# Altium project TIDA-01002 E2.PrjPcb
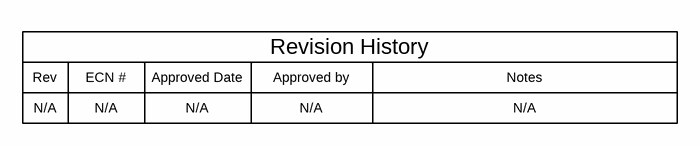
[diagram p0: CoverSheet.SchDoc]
CopyrightYear: 2016; EVM_Orderable: N/A; PCB_Layout: Krypton Solutions; PCB_Rev: E3; PRJ_Customer: Public Release; PRJ_Engineer: Luis Cordova; PRJ_Number: TIDA-01002; PRJ_Title: Automotive 1MP Camera Module with Image Correction; SCH_Rev: E3; TechSupport: http://www.ti.com/support; TID: TIDA-01002
5 sheets, 84 parts. Net scope: flat (ports and power ports of the same name join across sheets).
Board file: TIDA-01002 E2 Layout.PcbDoc
Sheets:
  CoverSheet.SchDoc
  Power over Coax Filter & Power Supply.SchDoc
  ON Semiconductor AS0140AT Imager + ISP.SchDoc
  Serializer.SchDoc
  TID_Hardware.SchDoc

## Sheet CoverSheet.SchDoc
size 431 x 279 mm; Date: Not shown in title block; ApprovedBy: Not shown in title block; CheckedBy: Not shown in title block; Author: Not shown in title block; CompanyName: Not shown in title block; Engineer: Not shown in title block; Organization: Not shown in title block; Address1: Not shown in title block; Address2: Not shown in title block; Address3: Not shown in title block; Address4: Not shown in title block; DocumentNumber: 1; Revision: Use project parameter SCH_Rev; SheetNumber: 1; SheetTotal: 5; PageSetup: Record=PageOptions¦CenterHorizontal=True¦CenterVertical=True¦PrintScale=1.00¦XCorrection=1.00¦YCorrection=1.00¦PrintKind=0¦BorderSize=5000000¦LeftOffset=0¦BottomOffset=0¦Orientation=2¦PaperLength=1000¦PaperWidth=1000¦Scale=100¦PaperSource=15¦PrintQuality=600¦MediaType=1¦DitherType=10¦PaperKind=Letter¦PrintScaleMode=1

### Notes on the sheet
- Rev
- N/A
- ECN #
- Approved Date
- Approved by
- Revision History
- Notes

## Sheet Power over Coax Filter & Power Supply.SchDoc
size 431 x 279 mm; Date: Not shown in title block; ApprovedBy: Not shown in title block; CheckedBy: Not shown in title block; Author: Not shown in title block; CompanyName: Not shown in title block; Engineer: Not shown in title block; Organization: Not shown in title block; Address1: Not shown in title block; Address2: Not shown in title block; Address3: Not shown in title block; Address4: Not shown in title block; DocumentNumber: 1; Revision: Use project parameter SCH_Rev; SheetNumber: 2; SheetTotal: 5; PageSetup: Record=PageOptions¦CenterHorizontal=True¦CenterVertical=True¦PrintScale=1.00¦XCorrection=1.00¦YCorrection=1.00¦PrintKind=0¦BorderSize=5000000¦LeftOffset=0¦BottomOffset=0¦Orientation=2¦PaperLength=1000¦PaperWidth=1000¦Scale=100¦PaperSource=15¦PrintQuality=600¦MediaType=1¦DitherType=10¦PaperKind=Letter¦PrintScaleMode=1
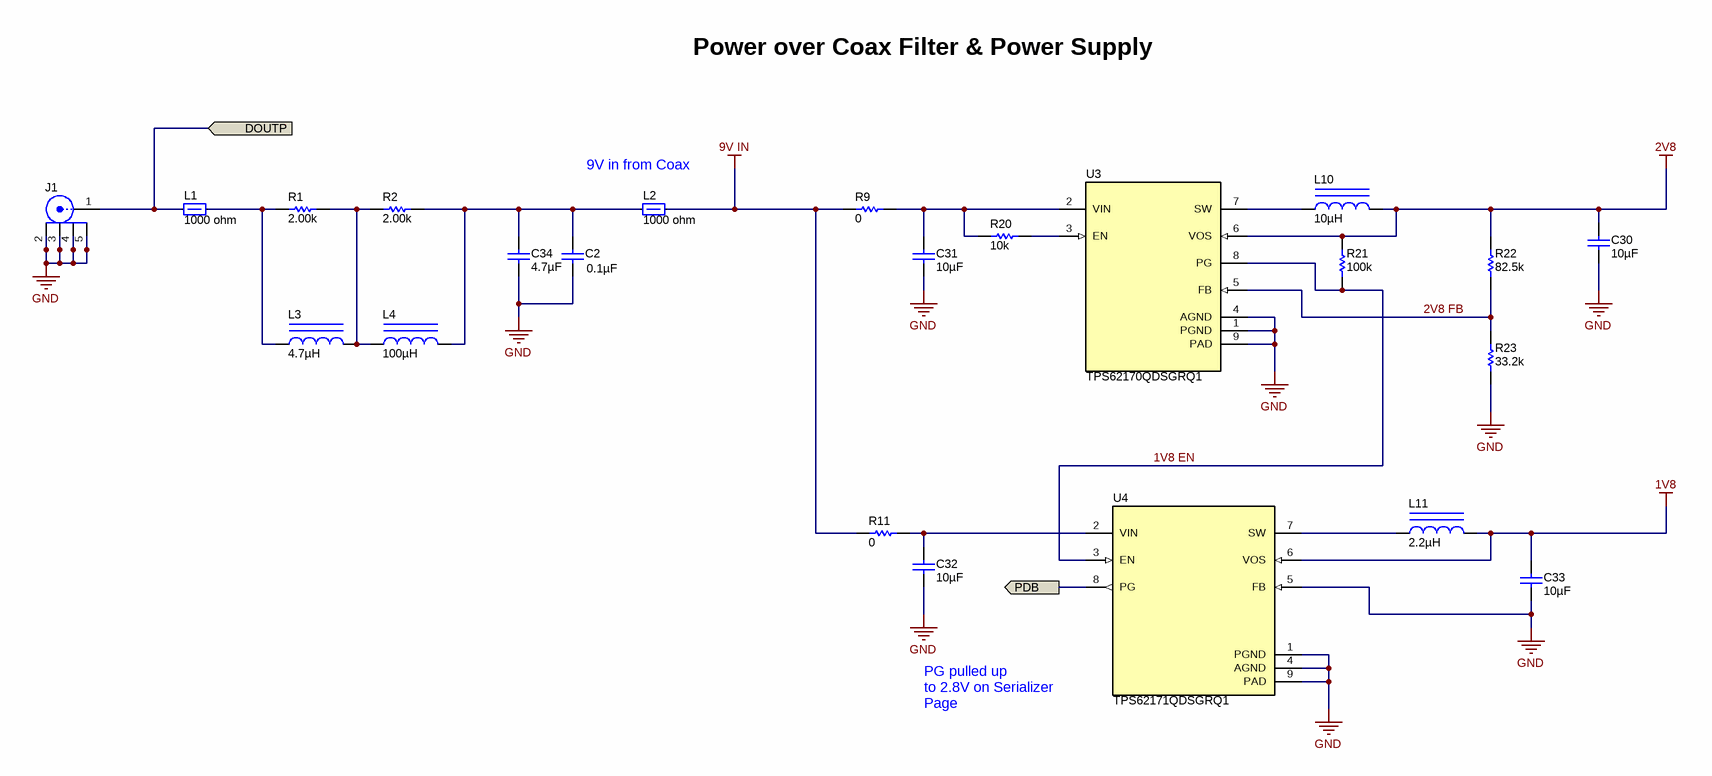
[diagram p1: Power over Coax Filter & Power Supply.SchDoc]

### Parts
C2  value 0.1µF  [0402L]  (hidden comment: C1005X7R1E104K050BB)
C30  ValueDisplayed: 10µF  [0805L]  (hidden comment: GRM21BR71A106KE51L)
C31  ValueDisplayed: 10µF  [0805L]  (hidden comment: CL21B106KOQNNNE)
C32  ValueDisplayed: 10µF  [0805L]  (hidden comment: CL21B106KOQNNNE)
C33  ValueDisplayed: 10µF  [0805L]  (hidden comment: GRM21BR71A106KE51L)
C34  ValueDisplayed: 4.7µF  [0603L]  (hidden comment: GRM188Z71C475KE21D)
J1  59S10H-40ML5-Z  [Rosenberger_59S10H-40ML5-Z]  (value not drawn)
L1  value 1000 ohm  [0402L]  (hidden comment: BLM15AX102SN1D)
L2  value 1000 ohm  [0402L]  (hidden comment: BLM15AX102SN1D)
L3  ValueDisplayed: 4.7µH  [CBC3225]  (hidden comment: CBC3225T4R7MR)
L4  ValueDisplayed: 100µH  [CBC3225]  (hidden comment: CBC3225T101MR)
L10  ValueDisplayed: 10µH  [WE-PMI_1008]  (hidden comment: 74479887310A)
L11  ValueDisplayed: 2.2µH  [WE-PMI-0805_1]  (hidden comment: 74479775222)
R1  ValueDisplayed: 2.00k  [0402L]  (hidden comment: CRCW04022K00FKED)
R2  ValueDisplayed: 2.00k  [0402L]  (hidden comment: CRCW04022K00FKED)
R9  value 0  [0402L]  (hidden comment: CRCW04020000Z0ED)
R11  value 0  [0402L]  (hidden comment: CRCW04020000Z0ED)
R20  ValueDisplayed: 10k  [0402L]  (hidden comment: CRCW040210K0JNED)
R21  ValueDisplayed: 100k  [0402L]  (hidden comment: CRCW0402100KFKED)
R22  ValueDisplayed: 82.5k  [0402L]  (hidden comment: CRCW040282K5FKED)
R23  ValueDisplayed: 33.2k  [0402L]  (hidden comment: CRCW040233K2FKED)
U3  TPS62170QDSGRQ1  [DSG0008A]
U4  TPS62171QDSGRQ1  [DSG0008A]

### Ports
DOUTP, PDB (out)

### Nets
1V8: C33.1 L11.2 U4.6(VOS)
2V8: C30.1 L10.2 R21.2 R22.2 U3.6(VOS)
9V IN: L2.2 R9.2 R11.2
GND: C2.2 C30.2 C31.2 C32.2 C33.2 C34.2 J1.2 J1.3 J1.4 J1.5 R23.1 U3.1(PGND) U3.4(AGND) U3.9(PAD) U4.1(PGND) U4.4(AGND) U4.5(FB) U4.9(PAD)
1V8 EN: R21.1 U3.8(PG) U4.3(EN)
2V8 FB: R22.1 R23.2 U3.5(FB)
DOUTP: J1.1 L1.1 ; port DOUTP
PDB: U4.8(PG) ; port PDB
NetC2_1: C2.1 C34.1 L2.1 L4.2 R2.1
NetC31_1: C31.1 R9.1 R20.1 U3.2(VIN)
NetC32_1: C32.1 R11.1 U4.2(VIN)
NetL1_2: L1.2 L3.1 R1.2
NetL3_2: L3.2 L4.1 R1.1 R2.2
NetL10_1: L10.1 U3.7(SW)
NetL11_1: L11.1 U4.7(SW)
NetR20_2: R20.2 U3.3(EN)

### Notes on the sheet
- Power over Coax Filter & Power Supply
- (near L2) 9V in from Coax
- (near U4) PG pulled up
  to 2.8V on Serializer
  Page

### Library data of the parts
C2 = C1005X7R1E103K: CAP, CERM, 0.1uF, 25V, +/-10%, X7R, 0402; Manufacturer: TDK Corporation; Tolerance_%: ±10%
C30 = GRM21BR71A106KE51L: CAP, CERM, 10uF, 10V, +/-10%, X7R, 0805; Manufacturer: MuRata; Polarized: N; CompType: Capacitor; U/M: EA; Cap_F: 0.00001; Tolerance_%: 10; ESR_Ohm: 0.003; Value1: 0.003 ohm; TaMin_C: -55; TaMax_C: 125; Cap_Case: 0805
C31 C32 = CL21B106KOQNNNE: CAP, CERM, 10 µF, 16 V, +/- 10%, X7R, 0805; Manufacturer: Samsung Electro-Mechanics; Polarized: N; CompType: Capacitor; Value: 10uF; U/M: EA; Cap_F: 0.00001; Tolerance_%: 10; Value1: Unknown; VDC_V: 16; Value2: 16V; TaMin_C: -55; TaMax_C: 125; Cap_Case: 0805; AEC Category: Q200; SizeArea_mm2: 2.5; SizeAreaWB_mm2: 6.75; SizeX_mm: 2; SizeY_mm: 1.25; SizeZ_mm: 1.45
C33 = GRM21BR71A106KE51L: CAP, CERM, 10 µF, 10 V, +/- 10%, X7R, 0805; Manufacturer: MuRata; Polarized: N; CompType: Capacitor; Value: 10uF; U/M: EA; Cap_F: 0.00001; Tolerance_%: 10; ESR_ohm: 0.003; Value1: 0.003 ohm; Value2: 10V; TaMin_C: -55; TaMax_C: 125; Cap_Case: 0805; AEC Category: Q200
C34 = GRM188Z71C475KE21D: CAP, CERM, 4.7 µF, 16 V,+/- 10%, X7R, 0603; Manufacturer: MuRata; Value: 4.7uF; VDC_V: 16; Tolerance_%: 10; Polarized: N; CompType: Capacitor; U/M: EA; Cap_F: 0.0000047; Value2: 16V; TaMin_C: -55; TaMax_C: 125; Cap_Case: 0603; SizeArea_mm2: 1.28; SizeAreaWB_mm2: 4.68; SizeX_mm: 1.6; SizeY_mm: 0.8; SizeZ_mm: 1; AEC Category: Q200
J1 = 59S10H-40ML5-Z: Connector, HF, 50 Ohm, TH; Manufacturer: Rosenberger; SymbolCreator: X0208326; Gender: Male; ContactFinish: Gold
L1 L2 = BLM15AX102SN1D: Ferrite Bead, 1000 ohm @ 100 MHz, 0.35 A, 0402; Manufacturer: MuRata; Imax_A: 0.35; DCR_ohm: 0.49; Value1: 0.49 ohm; Value2: 0.35A; ZTyp@100MHz_Ohm: 1000
L3 = CBC3225T4R7MR: Inductor, Wirewound, 4.7 µH, 1.01 A, 0.1 ohm, SMD; Manufacturer: Taiyo Yuden; Value: 4.7uH; Ind_H: 4.7E-6; Imax_A: 1.01; Irms: 1.04A @ 40C rise; Isat: 1.25A @ 30% inductance drop; DCR_ohm: 0.1; Value1: 0.1 ohm; Value2: 1.01A; AEC Category: Q200; AEC Qualified: N; SizeAreaWB_mm2: 14.7; SizeArea_mm2: 8; SizeX_mm: 3.2; SizeY_mm: 2.5; SizeZ_mm: 2.7; Green_Lifecycle: Active; Green_REACh: Passed
L4 = CBC3225T101MR: Inductor, Wirewound, 100 µH, 0.27 A, 1.4 ohm, SMD; Manufacturer: Taiyo Yuden; Value: 100uH; Ind_H: 100.0E-6; Imax_A: 0.27; Irms: 0.34A @ 40C rise; Isat: 0.27A @ 30% inductance drop; DCR_ohm: 1.4; Value1: 1.4 ohm; Value2: 0.27A; AEC Category: Q200; AEC Qualified: N; SizeAreaWB_mm2: 14.7; SizeArea_mm2: 8; SizeX_mm: 3.2; SizeY_mm: 2.5; SizeZ_mm: 2.7; Green_Lifecycle: Active; Green_REACh: Passed
L10 = 74479887310A: Inductor, Shielded Drum Core, Metal Composite, 10 µH, 0.125 A, 0.3 ohm, SMD; Manufacturer: Wurth Elektronik; Value: 10uH; Ind_H: 10.0E-6; Imax_A: 0.125; Irms: 0.85A @ 40C rise; Isat: 0.125A @ 30% inductance drop; DCR_ohm: 0.3; Value1: 0.3 ohm; Value2: 0.125A; AEC Category: Q200; AEC Qualified: N
L11 = 74479775222: Inductor, Shielded Drum Core, Metal Composite, 2.2 µH, 0.5 A, 0.23 ohm, SMD; Manufacturer: Wurth Elektronik; Value: 2.2uH; Ind_H: 2.2E-6; Imax_A: 0.5; Irms: 0.7A @ 40C rise; Isat: 0.5A @ 30% inductance drop; DCR_ohm: 0.23; Value2: 0.5A; AEC Category: Q200
R1 R2 = CRCW04022K00FKED: RES, 2.00 k, 1%, 0.063 W, 0402; Manufacturer: Vishay-Dale; CompType: Resistor; Value: 2.00k; Res_ohm: 2000; Value_Code: 2k00; Tolerance_%: 1; Power_W: 0.063; Value2: 0.063W; VDC_V: 50; TempCo: 100 ppm/C; EIA_Code: E96; U/M: EA; AEC Category: Q200
R9 R11 = CRCW04020000Z0ED: RES, 0 ohm, 5%, 0.063W, 0402; Manufacturer: Vishay-Dale; CompType: Resistor; Value_Code: 0000; Tolerance_%: 5; Power_W: 0.063; VDC_V: 50; TempCo: 200 ppm/C; EIA_Code: E24; U/M: EA
R20 = CRCW040210K0JNED: RES, 10 k, 5%, 0.063 W, 0402; Manufacturer: Vishay-Dale; CompType: Resistor; Value: 10k; Res_ohm: 10000; Value_Code: 10k0; Tolerance_%: 5; Power_W: 0.063; Value2: 0.063W; VDC_V: 50; TempCo: 200 ppm/C; EIA_Code: E24; U/M: EA; AEC Category: Q200
R21 = CRCW0402100KFKED: RES, 100 k, 1%, 0.063 W, 0402; Manufacturer: Vishay-Dale; CompType: Resistor; Value: 100k; Res_ohm: 100000; Tolerance_%: 1; Power_W: 0.063; Value2: 0.063W; VDC_V: 50; TempCo: 100 ppm/C; EIA_Code: E96; U/M: EA; AEC Category: Q200
R22 = CRCW040282K5FKED: RES, 82.5 k, 1%, 0.063 W, 0402; Manufacturer: Vishay-Dale; CompType: Resistor; Value: 82.5k; Res_ohm: 82500; Value_Code: 82k5; Tolerance_%: 1; Power_W: 0.063; Value2: 0.063W; VDC_V: 50; TempCo: 100 ppm/C; EIA_Code: E96; U/M: EA; AEC Category: Q200; SizeArea_mm2: 0.5; SizeZ_mm: 0.6
R23 = CRCW040233k2FKED: RES, 33.2 k, 1%, 0.063 W, 0402; Manufacturer: Vishay-Dale; CompType: Resistor; Value: 33.2k; Res_ohm: 33200; Value_Code: 33k2; Tolerance_%: 1; Power_W: 0.063; Value2: 0.063W; VDC_V: 50; TempCo: 100 ppm/C; EIA_Code: E96; U/M: EA; AEC Category: Q200; SizeArea_mm2: 0.5; SizeZ_mm: 0.6
U3 = TPS62170QDSGRQ1: 3-V to17-V 0.5-A Step-Down Converters with DCS-Control™, DSG0008A; Alternate PartNumber: TPS62170QDSGTQ1; Manufacturer: Texas Instruments; SymbolCreator: Altium; SizeArea_mm2: 4; SizeAreaWB_mm2: 9; SizeX_mm: 2; SizeZ_mm: 0.8; CompType: IC; U/M: EA
U4 = TPS62171QDSGRQ1: 3-V to 17-V, 0.5-A Step-Down Converter with DCS-Control, DSG0008A; Alternate PartNumber: TPS62171QDSGTQ1; Manufacturer: Texas Instruments; SymbolCreator: a0411947; SizeArea_mm2: 4; SizeAreaWB_mm2: 9; SizeX_mm: 2; SizeZ_mm: 0.8; CompType: IC; U/M: EA

## Sheet ON Semiconductor AS0140AT Imager + ISP.SchDoc
size 431 x 279 mm; Date: Not shown in title block; ApprovedBy: Not shown in title block; CheckedBy: Not shown in title block; Author: Not shown in title block; CompanyName: Not shown in title block; Engineer: Not shown in title block; Organization: Not shown in title block; Address1: Not shown in title block; Address2: Not shown in title block; Address3: Not shown in title block; Address4: Not shown in title block; DocumentNumber: 1; Revision: Use project parameter SCH_Rev; SheetNumber: 3; SheetTotal: 5; PageSetup: Record=PageOptions¦CenterHorizontal=True¦CenterVertical=True¦PrintScale=0.64¦XCorrection=1.00¦YCorrection=1.00¦PrintKind=0¦BorderSize=5000000¦LeftOffset=0¦BottomOffset=0¦Orientation=2¦PaperLength=1000¦PaperWidth=1000¦Scale=100¦PaperSource=15¦PrintQuality=600¦MediaType=1¦DitherType=10¦PrintScaleMode=1¦PaperKind=Letter
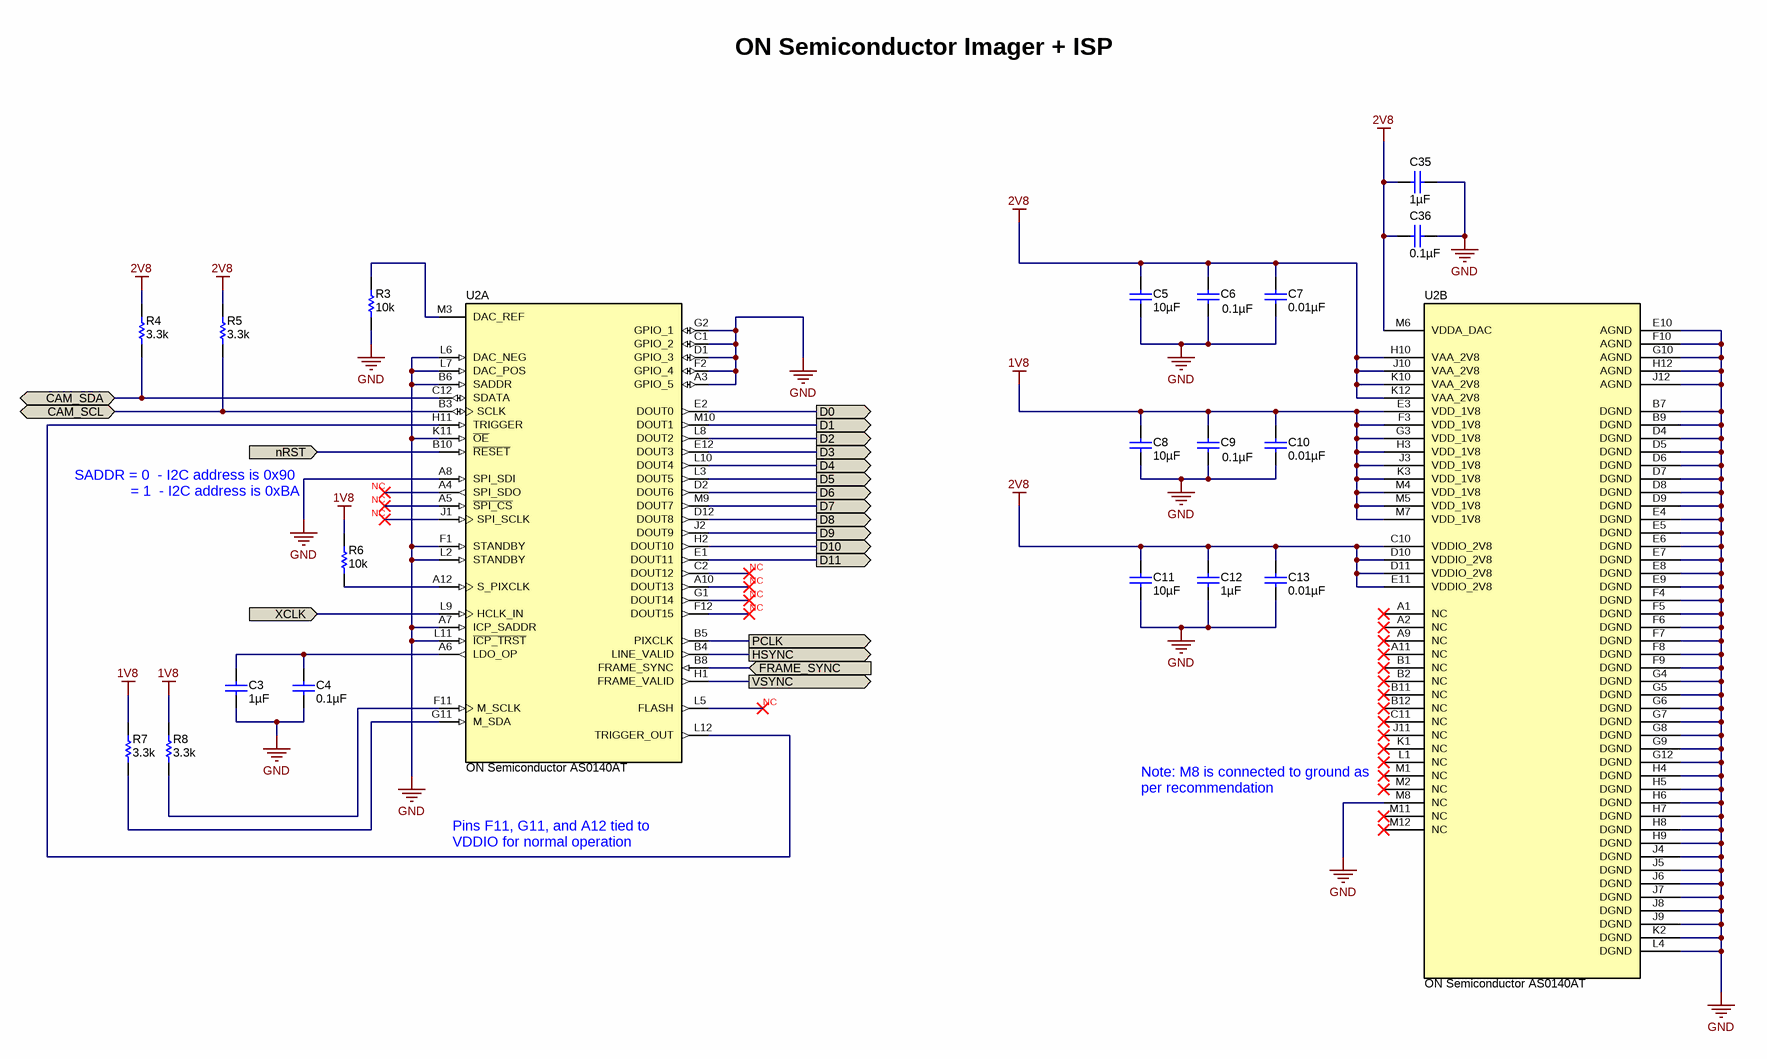
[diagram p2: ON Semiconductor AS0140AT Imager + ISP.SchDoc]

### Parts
C3  ValueDisplayed: 1µF  [0402L]  (hidden comment: GRM155R61A105KE15D)
C4  ValueDisplayed: 0.1µF  [0402L]  (hidden comment: GRM155R71C104KA88D)
C5  ValueDisplayed: 10µF  [0805L]  (hidden comment: GRM21BR71A106KE51L)
C6  value 0.1µF  [0402L]  (hidden comment: C1005X7R1E104K050BB)
C7  ValueDisplayed: 0.01µF  [0402L]  (hidden comment: GRM155R71C103KA01D)
C8  ValueDisplayed: 10µF  [0805L]  (hidden comment: GRM21BR71A106KE51L)
C9  value 0.1µF  [0402L]  (hidden comment: C1005X7R1E104K050BB)
C10  ValueDisplayed: 0.01µF  [0402L]  (hidden comment: GRM155R71C103KA01D)
C11  ValueDisplayed: 10µF  [0805L]  (hidden comment: GRM21BR71A106KE51L)
C12  ValueDisplayed: 1µF  [0402L]  (hidden comment: GRM155R61A105KE15D)
C13  ValueDisplayed: 0.01µF  [0402L]  (hidden comment: GRM155R71C103KA01D)
C35  ValueDisplayed: 1µF  [0402L]  (hidden comment: GRM155R61A105KE15D)
C36  value 0.1µF  [0402L]  (hidden comment: C1005X7R1E104K050BB)
R3  ValueDisplayed: 10k  [0402L]  (hidden comment: CRCW040210K0JNED)
R4  ValueDisplayed: 3.3k  [0402L]  (hidden comment: CRCW04023K30JNED)
R5  ValueDisplayed: 3.3k  [0402L]  (hidden comment: CRCW04023K30JNED)
R6  ValueDisplayed: 10k  [0402]  (hidden comment: CRCW040210K0JNED)
R7  ValueDisplayed: 3.3k  [0402]  (hidden comment: CRCW04023K30JNED)
R8  ValueDisplayed: 3.3k  [0402]  (hidden comment: CRCW04023K30JNED)
U2  ON Semiconductor AS0140AT  [BGA130_850x850x162]  (parts A,B of 2)

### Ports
CAM_SCL (bidir), CAM_SDA (bidir), D0 (out), D1 (out), D2 (out), D3 (out), D4 (out), D5 (out), D6 (out), D7 (out), D8 (out), D9 (out), D10 (out), D11 (out), FRAME_SYNC (in), HSYNC (out), nRST (in), PCLK (out), VSYNC (out), XCLK (in)

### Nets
1V8: C8.1 C9.1 C10.1 R6.2 R7.2 R8.2 U2.E3(VDD_1V8) U2.F3(VDD_1V8) U2.G3(VDD_1V8) U2.H3(VDD_1V8) U2.J3(VDD_1V8) U2.K3(VDD_1V8) U2.M4(VDD_1V8) U2.M5(VDD_1V8) U2.M7(VDD_1V8)
2V8: C5.1 C6.1 C7.1 C11.1 C12.1 C13.1 C35.1 C36.1 R4.2 R5.2 U2.C10(VDDIO_2V8) U2.D10(VDDIO_2V8) U2.D11(VDDIO_2V8) U2.E11(VDDIO_2V8) U2.H10(VAA_2V8) U2.J10(VAA_2V8) U2.K10(VAA_2V8) U2.K12(VAA_2V8) U2.M6(VDDA_DAC)
GND: C3.2 C4.2 C5.2 C6.2 C7.2 C8.2 C9.2 C10.2 C11.2 C12.2 C13.2 C35.2 C36.2 R3.1 U2.A3(GPIO_5) U2.A7(ICP_SADDR) U2.A8(SPI_SDI) U2.B6(SADDR) U2.B7(DGND) U2.B9(DGND) U2.C1(GPIO_2) U2.D1(GPIO_3) U2.D4(DGND) U2.D5(DGND) U2.D6(DGND) U2.D7(DGND) U2.D8(DGND) U2.D9(DGND) U2.E4(DGND) U2.E5(DGND) U2.E6(DGND) U2.E7(DGND) U2.E8(DGND) U2.E9(DGND) U2.E10(AGND) U2.F1(STANDBY) U2.F2(GPIO_4) U2.F4(DGND) U2.F5(DGND) U2.F6(DGND) U2.F7(DGND) U2.F8(DGND) U2.F9(DGND) U2.F10(AGND) U2.G2(GPIO_1) U2.G4(DGND) U2.G5(DGND) U2.G6(DGND) U2.G7(DGND) U2.G8(DGND) U2.G9(DGND) U2.G10(AGND) U2.G12(DGND) U2.H4(DGND) U2.H5(DGND) U2.H6(DGND) U2.H7(DGND) U2.H8(DGND) U2.H9(DGND) U2.H12(AGND) U2.J4(DGND) U2.J5(DGND) U2.J6(DGND) U2.J7(DGND) U2.J8(DGND) U2.J9(DGND) U2.J12(AGND) U2.K2(DGND) U2.K11(~{OE}) U2.L2(STANDBY) U2.L4(DGND) U2.L6(DAC_NEG) U2.L7(DAC_POS) U2.L11(~{ICP_TRST}) U2.M8(NC)
CAM_SCL: R5.1 U2.B3(SCLK) ; port CAM_SCL
CAM_SDA: R4.1 U2.C12(SDATA) ; port CAM_SDA
D0: U2.E2(DOUT0) ; port D0
D1: U2.M10(DOUT1) ; port D1
D2: U2.L8(DOUT2) ; port D2
D3: U2.E12(DOUT3) ; port D3
D4: U2.L10(DOUT4) ; port D4
D5: U2.L3(DOUT5) ; port D5
D6: U2.D2(DOUT6) ; port D6
D7: U2.M9(DOUT7) ; port D7
D8: U2.D12(DOUT8) ; port D8
D9: U2.J2(DOUT9) ; port D9
D10: U2.H2(DOUT10) ; port D10
D11: U2.E1(DOUT11) ; port D11
FRAME_SYNC: U2.B8(FRAME_SYNC) ; port FRAME_SYNC
HSYNC: U2.B4(LINE_VALID) ; port HSYNC
nRST: U2.B10(~{RESET}) ; port nRST
PCLK: U2.B5(PIXCLK) ; port PCLK
VSYNC: U2.H1(FRAME_VALID) ; port VSYNC
XCLK: U2.L9(HCLK_IN) ; port XCLK
NetC3_1: C3.1 C4.1 U2.A6(LDO_OP)
NetR3_2: R3.2 U2.M3(DAC_REF)
NetR6_1: R6.1 U2.A12(S_PIXCLK)
NetR7_1: R7.1 U2.G11(M_SDA)
NetR8_1: R8.1 U2.F11(M_SCLK)
NetU2_H11: U2.H11(TRIGGER) U2.L12(TRIGGER_OUT)

Not connected (* = marked no-connect by the designer): U2 A1(NC)* A2(NC)* A4(SPI_SDO)* A5(~{SPI_CS})* A9(NC)* A10(DOUT13)* A11(NC)* B1(NC)* B2(NC)* B11(NC)* B12(NC)* C2(DOUT12)* C11(NC)* F12(DOUT15)* G1(DOUT14)* J1(SPI_SCLK)* J11(NC)* K1(NC)* L1(NC)* L5(FLASH)* M1(NC)* M2(NC)* M11(NC)* M12(NC)*

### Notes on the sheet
- ON Semiconductor Imager + ISP
- NC
- SADDR = 0  - I2C address is 0x90
  = 1  - I2C address is 0xBA
- (near R6) NC
- Note: M8 is connected to ground as per recommendation
- Pins F11, G11, and A12 tied to VDDIO for normal operation

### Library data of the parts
C3 = GRM155R61A105KE15D: CAP, CERM, 1 µF, 10 V, +/- 10%, X5R, 0402; Manufacturer: MuRata; Polarized: N; CompType: Capacitor; Value: 1uF; U/M: EA; VDC_V: 10; Cap_F: 0.000001; Value1: Unknown; Value2: 10V; TaMin_C: -55; TaMax_C: 85; Cap_Case: 0402; AEC Category: Q200
C4 = GRM155R71C104KA88D: CAP, CERM, 0.1uF, 16V, +/-10%, X7R, 0402; Manufacturer: MuRata; Polarized: N; CompType: Capacitor; U/M: EA; Cap_F: 0.0000001; Tolerance_%: 10; Value1: Unknown; VDC_V: 16; TaMin_C: -55; TaMax_C: 125; Cap_Case: 0402
C5 C8 C11 = GRM21BR71A106KE51L: as C30 on sheet Power over Coax Filter & Power Supply
C6 C9 C36 = C1005X7R1E103K: as C2 on sheet Power over Coax Filter & Power Supply
C7 C10 C13 = GRM155R71C103KA01D: CAP, CERM, 0.01uF, 16V, +/-10%, X7R, 0402; Manufacturer: MuRata; Polarized: N; CompType: Capacitor; U/M: EA; Cap_F: 0.00000001; Tolerance_%: 10; Value1: Unknown; VDC_V: 16; TaMin_C: -55; TaMax_C: 125; Cap_Case: 0402
C12 C35 = GRM155R61A105KE15D: CAP, CERM, 1 µF, 10 V, +/- 10%, X5R, 0402; Manufacturer: MuRata; Polarized: N; CompType: Capacitor; Value: 1uF; U/M: EA; VDC_V: 10; Cap_F: 0.000001; Value1: Unknown; Value2: 10V; TaMin_C: -55; TaMax_C: 85; Cap_Case: 0402; SizeArea_mm2: 0.5; SizeAreaWB_mm2: 3; SizeX_mm: 1; SizeZ_mm: 0.6; AEC Category: Q200
R3 R6 = CRCW040210K0JNED: as R20 on sheet Power over Coax Filter & Power Supply
R4 R5 R7 R8 = CRCW04023K30JNED: RES, 3.3 k, 5%, 0.063 W, 0402; Manufacturer: Vishay-Dale; CompType: Resistor; Value: 3.3k; Res_ohm: 3300; Value_Code: 3k30; Tolerance_%: 5; Power_W: 0.063; Value2: 0.063W; VDC_V: 50; TempCo: 200 ppm/C; EIA_Code: E24; U/M: EA; AEC Category: Q200
U2 = AS0140: 1MP+ISP Single Package Solution, BGA130; SymbolCreator: Altium

## Sheet Serializer.SchDoc
size 431 x 279 mm; Date: Not shown in title block; ApprovedBy: Not shown in title block; CheckedBy: Not shown in title block; Author: Not shown in title block; CompanyName: Not shown in title block; Engineer: Not shown in title block; Organization: Not shown in title block; Address1: Not shown in title block; Address2: Not shown in title block; Address3: Not shown in title block; Address4: Not shown in title block; DocumentNumber: 1; Revision: Use project parameter SCH_Rev; SheetNumber: 4; SheetTotal: 5; PageSetup: Record=PageOptions¦CenterHorizontal=True¦CenterVertical=True¦PrintScale=1.00¦XCorrection=1.00¦YCorrection=1.00¦PrintKind=0¦BorderSize=5000000¦LeftOffset=0¦BottomOffset=0¦Orientation=2¦PaperLength=1000¦PaperWidth=1000¦Scale=100¦PaperSource=15¦PrintQuality=600¦MediaType=1¦DitherType=10¦PaperKind=Letter¦PrintScaleMode=1
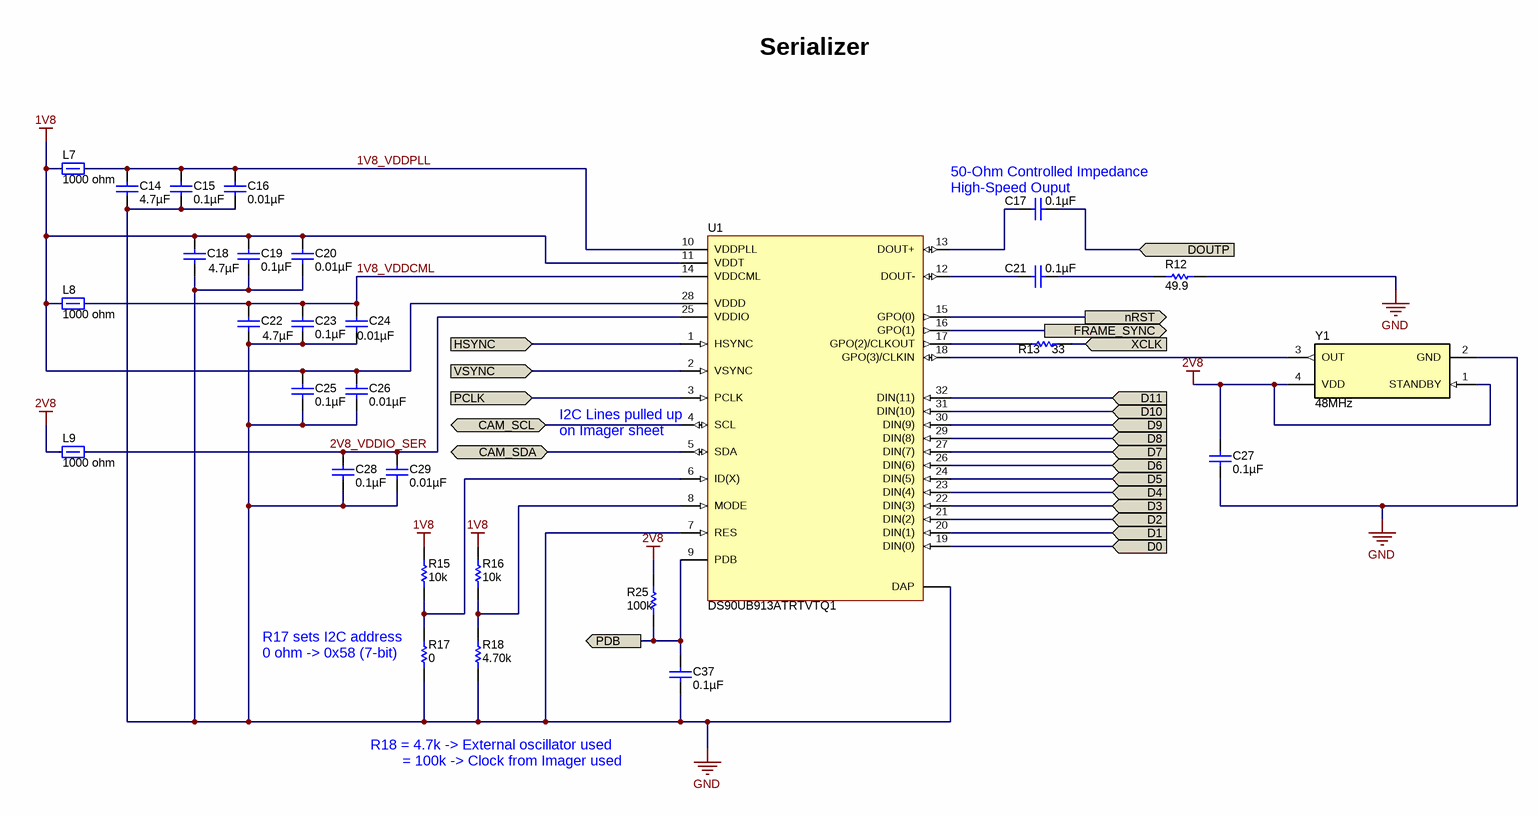
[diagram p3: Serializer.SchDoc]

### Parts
C14  ValueDisplayed: 4.7µF  [0603L]  (hidden comment: JMK107BB7475MA-T)
C15  ValueDisplayed: 0.1µF  [0402L]  (hidden comment: GRM155R71C104KA88D)
C16  ValueDisplayed: 0.01µF  [0402L]  (hidden comment: GRM155R71C103KA01D)
C17  ValueDisplayed: 0.1µF  [0402L]  (hidden comment: C1005X7R1H104K)
C18  value 4.7µF  [0603L]  (hidden comment: CL10B475KQ8NQNC)
C19  ValueDisplayed: 0.1µF  [0402L]  (hidden comment: GRM155R71C104KA88D)
C20  ValueDisplayed: 0.01µF  [0402L]  (hidden comment: GRM155R71C103KA01D)
C21  ValueDisplayed: 0.1µF  [0402L]  (hidden comment: C1005X7R1H104K)
C22  value 4.7µF  [0603L]  (hidden comment: CL10B475KQ8NQNC)
C23  ValueDisplayed: 0.1µF  [0402L]  (hidden comment: GRM155R71C104KA88D)
C24  ValueDisplayed: 0.01µF  [0402L]  (hidden comment: GRM155R71C103KA01D)
C25  ValueDisplayed: 0.1µF  [0402L]  (hidden comment: GRM155R71C104KA88D)
C26  ValueDisplayed: 0.01µF  [0402L]  (hidden comment: GRM155R71C103KA01D)
C27  ValueDisplayed: 0.1µF  [0402L]  (hidden comment: GRM155R71C104KA88D)
C28  ValueDisplayed: 0.1µF  [0402L]  (hidden comment: GRM155R71C104KA88D)
C29  ValueDisplayed: 0.01µF  [0402L]  (hidden comment: GRM155R71C103KA01D)
C37  ValueDisplayed: 0.1µF  [0402L]  (hidden comment: GRM155R71C104KA88D)
L7  value 1000 ohm  [0402L]  (hidden comment: BLM15AX102SN1D)
L8  value 1000 ohm  [0402L]  (hidden comment: BLM15AX102SN1D)
L9  value 1000 ohm  [0402L]  (hidden comment: BLM15AX102SN1D)
R12  value 49.9  [0402L]  (hidden comment: CRCW040249R9FKED)
R13  value 33  [0402L]  (hidden comment: CRCW040233R0JNED)
R15  value 10k  [0402L]  (hidden comment: CRCW040210K0JNED)
R16  value 10k  [0402L]  (hidden comment: CRCW040210K0JNED)
R17  value 0  [0402L]  (hidden comment: CRCW04020000Z0ED)
R18  ValueDisplayed: 4.70k  [0402L]  (hidden comment: CRG0402F4K7)
R25  ValueDisplayed: 100k  [0402L]  (hidden comment: CRCW0402100KFKED)
U1  DS90UB913ATRTVTQ1  [RTV0032A]
Y1  Frequency: 48MHz  [Abracon_ASDMB]  (hidden comment: ASDMB-48.000MHZ-LY-T)

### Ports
CAM_SCL (bidir), CAM_SDA (bidir), D0 (in), D1 (in), D2 (in), D3 (in), D4 (in), D5 (in), D6 (in), D7 (in), D8 (in), D9 (in), D10 (in), D11 (in), DOUTP, FRAME_SYNC (out), HSYNC (in), nRST (out), PCLK (in), PDB, VSYNC (in), XCLK

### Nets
1V8: C18.1 C19.1 C20.1 C25.1 C26.1 L7.1 L8.1 R15.2 R16.2 U1.11(VDDT) U1.28(VDDD)
2V8: C27.1 L9.1 R25.2 Y1.1(STANDBY) Y1.4(VDD)
GND: C14.2 C15.2 C16.2 C18.2 C19.2 C20.2 C22.2 C23.2 C24.2 C25.2 C26.2 C27.2 C28.2 C29.2 C37.2 R12.2 R17.1 R18.1 U1.7(RES) U1.33(DAP) Y1.2(GND)
1V8_VDDCML: C22.1 C23.1 C24.1 L8.2 U1.14(VDDCML)
1V8_VDDPLL: C14.1 C15.1 C16.1 L7.2 U1.10(VDDPLL)
2V8_VDDIO_SER: C28.1 C29.1 L9.2 U1.25(VDDIO)
CAM_SCL: U1.4(SCL) ; port CAM_SCL
CAM_SDA: U1.5(SDA) ; port CAM_SDA
D0: U1.19(DIN(0)) ; port D0
D1: U1.20(DIN(1)) ; port D1
D2: U1.21(DIN(2)) ; port D2
D3: U1.22(DIN(3)) ; port D3
D4: U1.23(DIN(4)) ; port D4
D5: U1.24(DIN(5)) ; port D5
D6: U1.26(DIN(6)) ; port D6
D7: U1.27(DIN(7)) ; port D7
D8: U1.29(DIN(8)) ; port D8
D9: U1.30(DIN(9)) ; port D9
D10: U1.31(DIN(10)) ; port D10
D11: U1.32(DIN(11)) ; port D11
DOUTP: C17.1 ; port DOUTP
FRAME_SYNC: U1.16(GPO(1)) ; port FRAME_SYNC
HSYNC: U1.1(HSYNC) ; port HSYNC
nRST: U1.15(GPO(0)) ; port nRST
PCLK: U1.3(PCLK) ; port PCLK
PDB: C37.1 R25.1 U1.9(PDB) ; port PDB
VSYNC: U1.2(VSYNC) ; port VSYNC
XCLK: R13.2 ; port XCLK
NetC17_2: C17.2 U1.13(DOUT+)
NetC21_1: C21.1 R12.1
NetC21_2: C21.2 U1.12(DOUT-)
NetR13_1: R13.1 U1.17(GPO(2)/CLKOUT)
NetR15_1: R15.1 R17.2 U1.6(ID(X))
NetR16_1: R16.1 R18.2 U1.8(MODE)
NetU1_18: U1.18(GPO(3)/CLKIN) Y1.3(OUT)

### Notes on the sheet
- Serializer
- (near C17) 50-Ohm Controlled Impedance High-Speed Ouput
- (near U1) I2C Lines pulled up
  on Imager sheet
- (near R17) R17 sets I2C address
  0 ohm -> 0x58 (7-bit)
- R18 = 4.7k -> External oscillator used
  = 100k -> Clock from Imager used

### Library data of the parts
C14 = JMK107BB7475MA-T: CAP, CERM, 4.7 µF, 6.3 V, +/- 10%, X7R, 0603; Manufacturer: Taiyo Yuden; Polarized: N; CompType: Capacitor; Value: 4.7uF; U/M: EA; Cap_F: 0.0000047; Tolerance_%: 10; Value1: Unknown; VDC_V: 6.3; Value2: 6.3V; TaMin_C: -55; TaMax_C: 125; Cap_Case: 0603; AEC Category: Q200
C15 = GRM155R71C104KA88D: CAP, CERM, 0.1 µF, 16 V, +/- 10%, X7R, 0402; Manufacturer: MuRata; Polarized: N; CompType: Capacitor; Value: 0.1uF; U/M: EA; Cap_F: 0.0000001; Tolerance_%: 10; Value1: Unknown; VDC_V: 16; Value2: 16V; TaMin_C: -55; TaMax_C: 125; Cap_Case: 0402; AEC Category: Q200
C16 C20 C24 C26 C29 = GRM155R71C103KA01D: as C7 on sheet ON Semiconductor AS0140AT Imager + ISP
C17 C21 = C1005X7R1H104K: CAP, CERM, 0.1uF, 50V, +/-10%, C0G/NP0, 0402; Manufacturer: TDK; Polarized: N; CompType: Capacitor; U/M: EA; Cap_F: 0.0000001; Tolerance_%: 10; Value1: Unknown; VDC_V: 50; TaMin_C: -55; TaMax_C: 125; Cap_Case: 0402
C18 C22 = Capacitor: CAP CER 4.7UF 6.3V 10% X7R 0603; Manufacturer: Samsung Electro-Mechanics America, Inc; Polarized: N; U/M: EA
C19 C23 C25 C27 C28 C37 = GRM155R71C104KA88D: as C4 on sheet ON Semiconductor AS0140AT Imager + ISP
L7-L9 = BLM15AX102SN1D: as L1 on sheet Power over Coax Filter & Power Supply
R12 = CRCW040249R9FKED: RES, 49.9 ohm, 1%, 0.063W, 0402; Manufacturer: Vishay-Dale; CompType: Resistor; Value_Code: 49R9; Tolerance_%: 1; Power_W: 0.063; VDC_V: 50; TempCo: 100 ppm/C; EIA_Code: E96; U/M: EA
R13 = CRCW040233R0JNED: RES, 33 ohm, 5%, 0.063W, 0402; Manufacturer: Vishay-Dale; CompType: Resistor; Value_Code: 33R0; Tolerance_%: 5; Power_W: 0.063; VDC_V: 50; TempCo: 200 ppm/C; EIA_Code: E24; U/M: EA
R15 R16 = CRCW040210K0JNED: RES, 10k ohm, 5%, 0.063W, 0402; Manufacturer: Vishay-Dale; CompType: Resistor; Res_ohm: 10000; Value_Code: 10k0; Tolerance_%: 5; Power_W: 0.063; VDC_V: 50; TempCo: 200 ppm/C; EIA_Code: E24; U/M: EA
R17 = CRCW04020000Z0ED: as R9 on sheet Power over Coax Filter & Power Supply
R18 = CRG0402F4K7: RES, 4.70 k, 1%, 0.063 W, 0402; Manufacturer: TE Connectivity; CompType: Resistor; Value: 4.70k; Res_ohm: 4700; Value_Code: 4k70; Tolerance_%: 1; Power_W: 0.063; Value2: 0.063W; TempCo: 100 ppm/C; U/M: EA; AEC Category: Q200; AEC Qualified: N
R25 = CRCW0402100KFKED: as R21 on sheet Power over Coax Filter & Power Supply
U1 = DS90UB913ATRTVTQ1: DS90UB913A-Q1/DS90UB914A-Q1 25 to 100 MHz 10/20-Bit FPD-Link III Serializer and Deserializer, RTV0032A; Alternate Manufacturer: None; Manufacturer: Texas Instruments; SymbolCreator: x0208325; CompType: IC; U/M: EA
Y1 = ASDMB-48.000MHZ-LY-T: OSC, 48MHz, 1.8 to 3.3V, SMD; Manufacturer: Abracon Corporation; SymbolCreator: Altium; CompType: Oscillator; U/M: EA; TaMin_C: -40; TaMax_C: 85; Frequency Stability: ±10ppm

## Sheet TID_Hardware.SchDoc
size 431 x 279 mm; Date: Not shown in title block; ApprovedBy: Not shown in title block; CheckedBy: Not shown in title block; Author: Not shown in title block; CompanyName: Not shown in title block; Engineer: Not shown in title block; Organization: Not shown in title block; Address1: Not shown in title block; Address2: Not shown in title block; Address3: Not shown in title block; Address4: Not shown in title block; DocumentNumber: 1; Revision: Use project parameter SCH_Rev; SheetNumber: 5; SheetTotal: 5; PageSetup: Record=PageOptions¦CenterHorizontal=True¦CenterVertical=True¦PrintScale=1.00¦XCorrection=1.00¦YCorrection=1.00¦PrintKind=0¦BorderSize=5000000¦LeftOffset=0¦BottomOffset=0¦Orientation=2¦PaperLength=1000¦PaperWidth=1000¦Scale=100¦PaperSource=15¦PrintQuality=600¦MediaType=1¦DitherType=10¦PaperKind=Letter¦PrintScaleMode=1
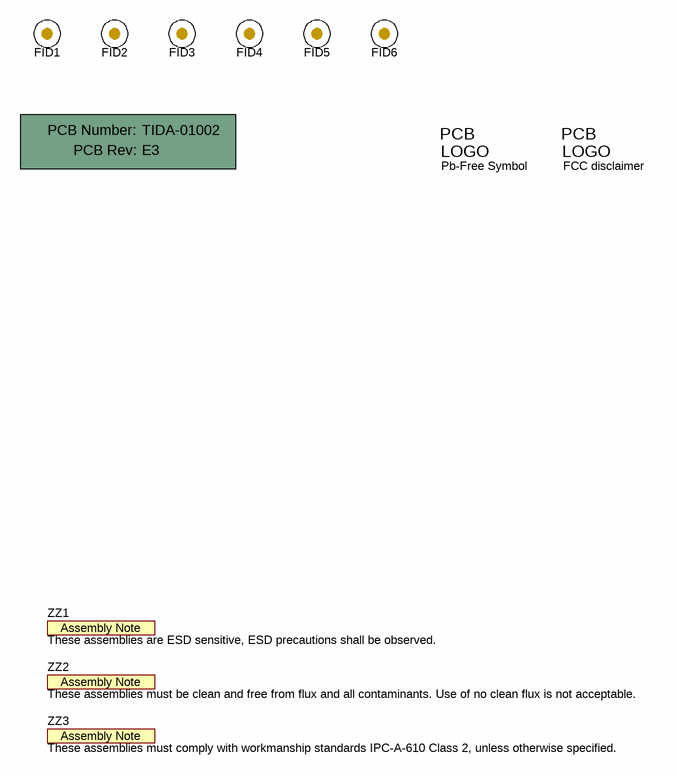
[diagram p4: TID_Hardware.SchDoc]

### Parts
!PCB1  Printed Circuit Board  (value not drawn)  (mechanical)
FID1  Fiducial  [Fiducial10-20]  (value not drawn)
FID2  Fiducial  [Fiducial10-20]  (value not drawn)
FID3  Fiducial  [Fiducial10-20]  (value not drawn)
FID4  Fiducial  [Fiducial10-20]  (value not drawn)
FID5  Fiducial  [Fiducial10-20]  (value not drawn)
FID6  Fiducial  [Fiducial10-20]  (value not drawn)
Logo2  Pb-Free Symbol  [Pb-Free_Overlay_Small]  (no BOM)
Logo3  FCC disclaimer  [FCC_disclaimer_stacked]  (no BOM)
ZZ1  These assemblies are ESD sensitive, ESD precautions shall be observed.  [AssemblyNote]  (no BOM)
ZZ2  These assemblies must be clean and free from flux and all contaminants. Use of no clean flux is not acceptable.  [AssemblyNote]  (no BOM)
ZZ3  These assemblies must comply with workmanship standards IPC-A-610 Class 2, unless otherwise specified.  [AssemblyNote]  (no BOM)

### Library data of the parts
!PCB1 = PCB: Manufacturer: Any; PartNumber: TIDA-01002; SymbolCreator: a0412235
FID1-FID6 = Fiducial: Fiducial mark.  There is nothing to buy or mount.; SymbolCreator: codlsc
Logo2 = Pb-Free: SymbolCreator: a0412235
Logo3 = FCC_disclaimer: SymbolCreator: a0412235
ZZ1-ZZ3 = AssemblyNote: SymbolCreator: codlsc

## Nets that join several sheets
1V8: Power over Coax Filter & Power Supply (C33.1 L11.2 U4.6), ON Semiconductor AS0140AT Imager + ISP (15 pins), Serializer (11 pins)
2V8: Power over Coax Filter & Power Supply (5 pins), ON Semiconductor AS0140AT Imager + ISP (19 pins), Serializer (5 pins)
GND: Power over Coax Filter & Power Supply (18 pins), ON Semiconductor AS0140AT Imager + ISP (75 pins), Serializer (21 pins)
CAM_SCL: ON Semiconductor AS0140AT Imager + ISP (R5.1 U2.B3), Serializer (U1.4)
CAM_SDA: ON Semiconductor AS0140AT Imager + ISP (R4.1 U2.C12), Serializer (U1.5)
D0: ON Semiconductor AS0140AT Imager + ISP (U2.E2), Serializer (U1.19)
D1: ON Semiconductor AS0140AT Imager + ISP (U2.M10), Serializer (U1.20)
D2: ON Semiconductor AS0140AT Imager + ISP (U2.L8), Serializer (U1.21)
D3: ON Semiconductor AS0140AT Imager + ISP (U2.E12), Serializer (U1.22)
D4: ON Semiconductor AS0140AT Imager + ISP (U2.L10), Serializer (U1.23)
D5: ON Semiconductor AS0140AT Imager + ISP (U2.L3), Serializer (U1.24)
D6: ON Semiconductor AS0140AT Imager + ISP (U2.D2), Serializer (U1.26)
D7: ON Semiconductor AS0140AT Imager + ISP (U2.M9), Serializer (U1.27)
D8: ON Semiconductor AS0140AT Imager + ISP (U2.D12), Serializer (U1.29)
D9: ON Semiconductor AS0140AT Imager + ISP (U2.J2), Serializer (U1.30)
D10: ON Semiconductor AS0140AT Imager + ISP (U2.H2), Serializer (U1.31)
D11: ON Semiconductor AS0140AT Imager + ISP (U2.E1), Serializer (U1.32)
DOUTP: Power over Coax Filter & Power Supply (J1.1 L1.1), Serializer (C17.1)
FRAME_SYNC: ON Semiconductor AS0140AT Imager + ISP (U2.B8), Serializer (U1.16)
HSYNC: ON Semiconductor AS0140AT Imager + ISP (U2.B4), Serializer (U1.1)
nRST: ON Semiconductor AS0140AT Imager + ISP (U2.B10), Serializer (U1.15)
PCLK: ON Semiconductor AS0140AT Imager + ISP (U2.B5), Serializer (U1.3)
PDB: Power over Coax Filter & Power Supply (U4.8), Serializer (C37.1 R25.1 U1.9)
VSYNC: ON Semiconductor AS0140AT Imager + ISP (U2.H1), Serializer (U1.2)
XCLK: ON Semiconductor AS0140AT Imager + ISP (U2.L9), Serializer (R13.2)

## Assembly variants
001: not fitted FID1 FID2 FID3 FID4 FID5 FID6 R19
